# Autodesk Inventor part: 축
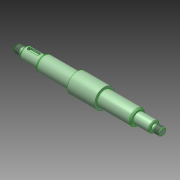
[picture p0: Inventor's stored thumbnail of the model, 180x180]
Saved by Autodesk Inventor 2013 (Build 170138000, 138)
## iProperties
Created: 2011-02
Part Number: 축
Document SubType Name: Modeling
Designer: pww
Density: 1 g/cm^3
Material: 강철, 연강
Author: pww
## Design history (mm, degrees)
sketch "스케치1"
  geometry: L1 (0, 0)-(192, 0); L2 (0, 0)-(0, 5); L3 (0, 5)-(7.008, 5); L4 (9, 3.85)-(11, 3.85); L5 (11, 3.85)-(11, 7.5); L6 (11, 7.5)-(34, 7.5); L7 (34, 7.5)-(34, 8.273); L8 (36.528, 10)-(78.4, 10); L9 (79, 10.6)-(79, 13); L10 (79, 13)-(115, 13); L11 (115, 13)-(115, 10.6); L12 (115.6, 10)-(157.472, 10); L13 (160, 8.273)-(160, 7); L14 (160, 7)-(181, 7); L15 (181, 7)-(181, 3.85); L16 (181, 3.85)-(183, 3.85); L17 (184.992, 5)-(192, 5); L18 (192, 5)-(192, 0); L19 (79, 22.9)-(79, -22.9) reference; L20 (115, 22.9)-(115, -22.9) reference; L21 (9, 3.85)-(7.008, 5); L22 (183, 3.85)-(184.992, 5); L23 (34.5, 9.139)-(35.528, 9.732); L24 (159.5, 9.139)-(158.472, 9.732); A1 r 0.6 centre (78.4, 10.6) between (78.4, 10) and (79, 10.6); A2 r 0.6 centre (115.6, 10.6) between (115, 10.6) and (115.6, 10); A3 r 2 centre (36.528, 8) between (36.528, 10) and (35.528, 9.732); A4 r 1 centre (35, 8.273) between (34.5, 9.139) and (34, 8.273); A5 r 1 centre (159, 8.273) between (160, 8.273) and (159.5, 9.139); A6 r 2 centre (157.472, 8) between (158.472, 9.732) and (157.472, 10); 5 further points
  constraints: 44 end point, 12 point on circle, 12 tangent, 10 parallel, 10 point on line, 6 centre point, 6 perpendicular, 4 collinear, 2 horizontal, 1 equal radius
  dimensions: "d0" = 192 distance of L1.start L1.end; "d1" = 10 diameter of L3 L1; "d3" = 7.7 diameter of L4 L1; "d4" = 2 distance of L4.start L4.end; "d5" = 15 diameter of L6 L1; "d6" = 23 distance of L5.end L6.end; "d7" = 20 diameter of L8 L1; "d10" = 10 diameter of L17 L1; "d12" = 2 distance of L15.end L16.end; "d13" = 21 distance of L13.end L14.end; "d14" = 11 distance between parallel lines of L18 L15; "d15" = 14 diameter of L14 L1; "d35" = 11 distance between parallel lines of L5 L2; "d36" = 3 distance between parallel lines of L10 L8; "d37" = 0.6 radius of A1; "d39" = 30 deg angle of L21 L4; "d40" = 30 deg angle of L22 L16; "d42" = 30 deg angle of L8 L23; "d43" = 17.7 diameter of point (34, 8.85) L1; "d44" = 2 radius of A3; "d45" = 1 radius of A4; "d46" = 30 deg angle of L12 L24; "d47" = 17.7 diameter of point (160, 8.85) L1; "d48" = 1 radius of A5; "d49" = 2 radius of A6
revolve "회전1" sketch "스케치1" stored, may be unused: angle "d17" = 90 deg
feature "스레드1" dims "d18" = 10, "d19" = 0
feature "스레드2" dims "d20" = 10, "d21" = 0
chamfer "모따기1" distance "d22" = 1; stored, may be unused: second distance "d23" = 2, angle "d24" = 45 deg
node "작업 평면1"
sketch "스케치2"
  geometry: L1 (-6, 2.5)-(5, 2.5); L2 (5, -2.5)-(-6, -2.5); L3 (11.5, -8.273)-(11.5, 8.273) reference; A1 r 2.5 centre (5, 0) between (5, -2.5) and (5, 2.5); A2 r 2.5 centre (-6, 0) between (-6, 2.5) and (-6, -2.5); 1 further point
  constraints: 4 end point, 4 point on circle, 4 tangent, 2 centre point, 1 horizontal, 1 horizontal alignment, 1 parallel
  dimensions: "d25" = 5 distance between parallel lines of L2 L1; "d27" = 16 dimension on A1 A2; "d50" = 4 distance edge to line of A1 L3
extrude "돌출1" cut sketch "스케치2" distance "d28" = 3; taper "d29" = 0 deg
node "작업 평면2"
sketch "스케치3"
  geometry: L1 (-5, 2.5)-(6, 2.5); L2 (6, -2.5)-(-5, -2.5); L3 (-10.5, -6)-(-10.5, 6) reference; A1 r 2.5 centre (6, 0) between (6, -2.5) and (6, 2.5); A2 r 2.5 centre (-5, 0) between (-5, 2.5) and (-5, -2.5); 1 further point
  constraints: 4 end point, 4 point on circle, 4 tangent, 2 centre point, 1 horizontal, 1 horizontal alignment, 1 parallel
  dimensions: "d30" = 3 distance edge to line of A2 L3; "d31" = 5 distance between parallel lines of L2 L1; "d32" = 16 dimension on A1 A2
extrude "돌출2" cut sketch "스케치3" distance "d33" = 3; taper "d34" = 0 deg
node "솔리드1"
node "참조1"
node "참조2"
